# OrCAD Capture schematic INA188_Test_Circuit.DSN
size A; title: INA188 Precision, Zero-Drift, Rail-to-Rail Out, High-Voltage; rev: 1.1; note: Datasheet: SBOS632 EVM: N/A
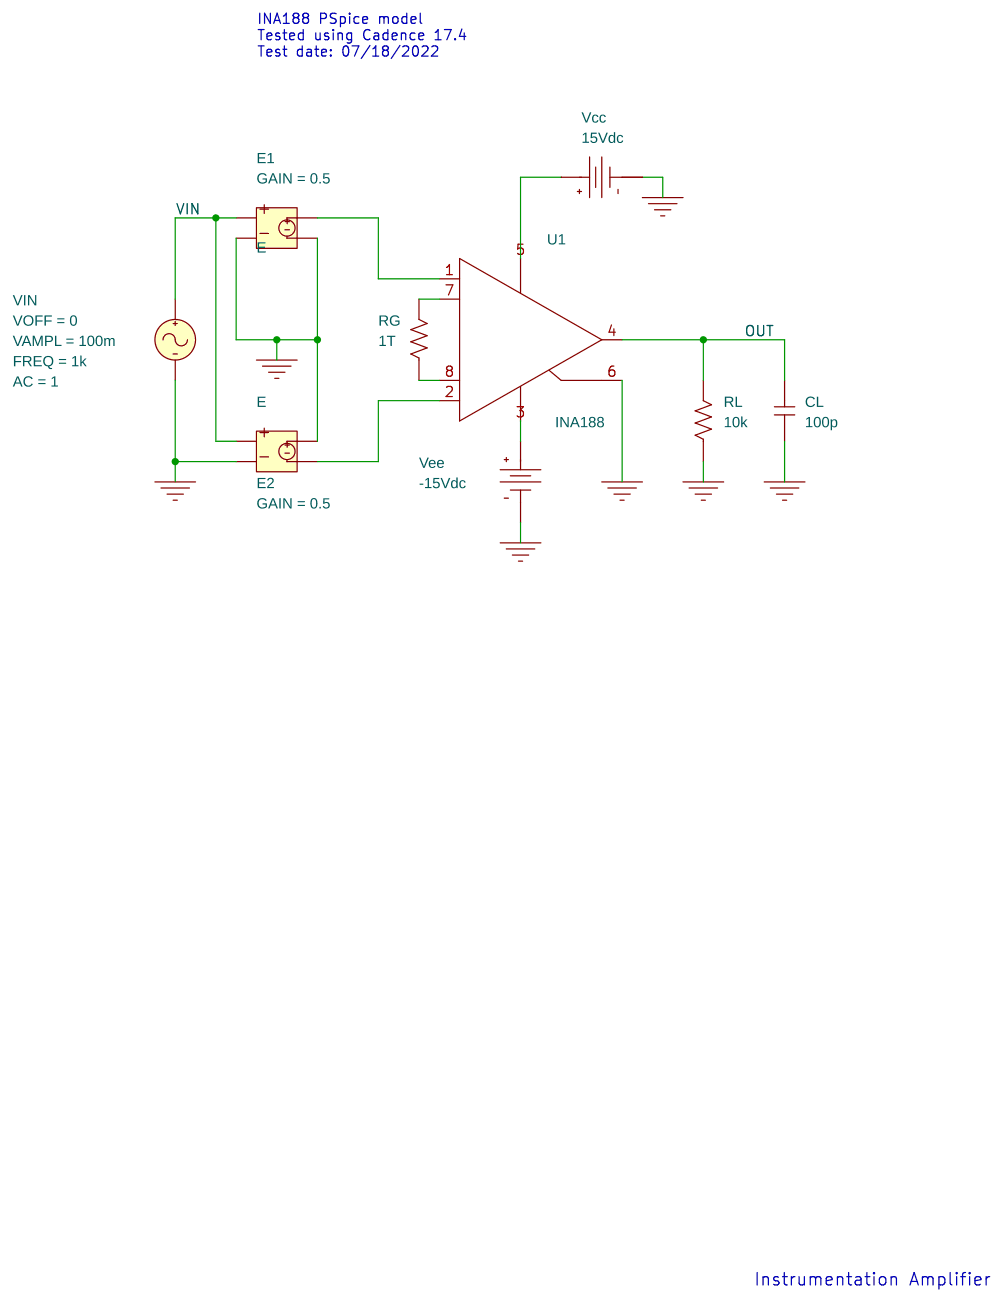
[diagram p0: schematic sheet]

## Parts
CL  100p  [RAD/CK05]
E1  E
E2  E
RG  1T  [AX/RC05]
RL  10k  [AX/RC05]
U1  INA188
Vcc  VDC
Vee  VDC
VIN  VSIN

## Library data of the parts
CL = C
E1 E2 = E: GAIN: 0.5
RG RL = R
U1 = INA188
Vcc = VDC: DC: 15Vdc
Vee = VDC: DC: -15Vdc
VIN = VSIN: AC: 1; FREQ: 1k; VAMPL: 100m; VOFF: 0

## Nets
VIN: E1.1 E2.1 VIN.1(+)
0: CL.1 E1.2 E1.4 E2.2 E2.3 RL.1 U1.6(REF) Vcc.1(-) Vee.1(-) VIN.2(-)
OUT: CL.2 RL.2 U1.4(OUT)
N11906: U1.5(V+) Vcc.0(+)
N12164: E1.3 U1.1(+)
N12256: E2.4 U1.2(-)
N12296: U1.3(V-) Vee.0(+)
N24516: RG.2 U1.7(RG+)
N24544: RG.1 U1.8(RG-)

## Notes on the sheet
- INA188 PSpice model
  Tested using Cadence 17.4
  Test date: 07/18/2022
- Instrumentation Amplifier
